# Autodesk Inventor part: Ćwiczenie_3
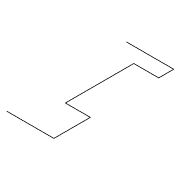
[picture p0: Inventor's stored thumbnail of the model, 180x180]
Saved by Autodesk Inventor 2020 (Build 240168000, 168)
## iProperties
Created: 2005-01
Part Number: Ćwiczenie_3
Document SubType Name: Modeling
Designer: F.Stasiak
Manufacturer: Standard
Standards Organization: Custom
Density: 1 g/cm^3
Material: Ogólny
Appearance: Domyślna
Manager: www.cadconsulting.pl
Company: Fabian Stasiak CAD Consulting
Author: F.Stasiak
Subject: Zbiór ćwiczeń. Autodesk Inventor 2020. Kurs podstawowy
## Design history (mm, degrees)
sketch "Szkic1"
  geometry: L1 (50.119, 55.795)-(67.802, 55.795); L2 (67.802, 55.795)-(67.802, 50.179); L3 (67.802, 50.179)-(58.483, 50.179); L4 (58.483, 50.179)-(58.483, 24.612); L5 (58.483, 24.612)-(67.802, 24.612); L6 (67.802, 24.612)-(67.802, 10.992); L7 (67.802, 10.992)-(50.119, 10.992)
  constraints: 14 end point, 4 parallel, 2 collinear, 1 horizontal, 1 perpendicular, 1 other
node "Korpusy bryłowe"
node "Korpusy powierzchniowe"
